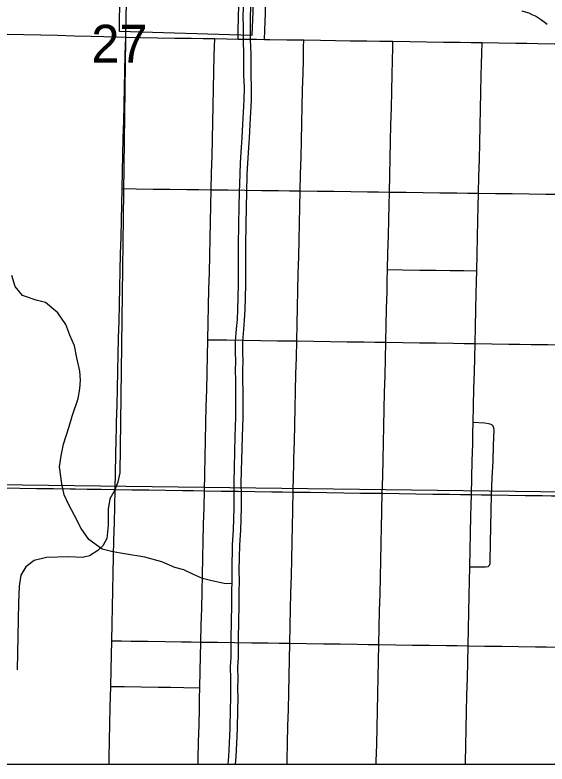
# Model space of a CAD drawing. Extents: x 0 to 34, y 0 to 22.
# Drawn here: x 5.12 to 5.71, y 14.1 to 14.929 of the extents above; entities that cross this region are included whole.
import ezdxf

# ---------------------------------------------------------------- set-up
doc = ezdxf.new("R2010")
doc.units = 0
for name, color, linetype in [('GM_X_City_Street', 7, 'Continuous'), ('GM_X_Corporation', 7, 'Continuous'), ('GM_X_County_Road', 7, 'Continuous'), ('GM_X_Minor_River', 7, 'Continuous'), ('GM_X_Rail_Line', 7, 'Continuous'), ('GM_X_Section_Text', 7, 'Continuous'), ('GM_X_State_Shield', 7, 'Continuous'), ('GM_X_Township_Road', 7, 'Continuous'), ('SH_Data', 7, 'Continuous')]:
    doc.layers.add(name, color=color, linetype=linetype)

msp = doc.modelspace()

# ---------------------------------------------------------------- linework, layer by layer
at = {"layer": 'GM_X_City_Street'}
msp.add_line((5.2326, 14.47067), (5.23264, 14.47263), dxfattribs=at)
for points in [[(5.39671, 14.9023), (5.39702, 14.91248), (5.39758, 14.93111), (5.39815, 14.94975), (5.39871, 14.96838), (5.39927, 14.98702), (5.39984, 15.00565), (5.40022, 15.01854), (5.40061, 15.03142)], [(5.23264, 14.47263), (5.23278, 14.47851), (5.23322, 14.49715), (5.23366, 14.51578), (5.23409, 14.53442), (5.23453, 14.55305), (5.23497, 14.57169), (5.23541, 14.59032), (5.23585, 14.60896), (5.23629, 14.62759), (5.23672, 14.64623), (5.23716, 14.66486), (5.2376, 14.6835), (5.23804, 14.70213), (5.23845, 14.7196), (5.23886, 14.73706), (5.23929, 14.7557), (5.23973, 14.77433), (5.24017, 14.79297), (5.24061, 14.8116), (5.24105, 14.83023), (5.24148, 14.84887), (5.24191, 14.86721), (5.24234, 14.88555), (5.24257, 14.89522), (5.2428, 14.90489)], [(5.42905, 14.43012), (5.42925, 14.4384), (5.42969, 14.45703), (5.43012, 14.47567), (5.43056, 14.4943), (5.431, 14.51294), (5.43144, 14.53157), (5.43187, 14.54999), (5.4323, 14.56841), (5.43274, 14.58705), (5.43317, 14.60568), (5.43362, 14.62432), (5.43405, 14.64295), (5.43449, 14.66159), (5.43493, 14.68022), (5.43537, 14.69886), (5.43578, 14.71671), (5.43621, 14.73456), (5.43664, 14.75319), (5.43708, 14.77183), (5.43751, 14.79046), (5.43795, 14.8091), (5.43839, 14.82773), (5.43883, 14.84637), (5.43926, 14.865), (5.4396, 14.87939), (5.43994, 14.89377), (5.44013, 14.90165)], [(5.52706, 14.39971), (5.5275, 14.41834), (5.52795, 14.43698), (5.52839, 14.45561), (5.52883, 14.47425), (5.52927, 14.49288), (5.5297, 14.51152), (5.53014, 14.53015), (5.53058, 14.54857), (5.53101, 14.56698), (5.53145, 14.58561), (5.53189, 14.60425), (5.53233, 14.62288), (5.53262, 14.63512), (5.5329, 14.64737), (5.53334, 14.666), (5.53379, 14.68464), (5.53423, 14.70327), (5.53458, 14.71828), (5.53494, 14.7333), (5.53538, 14.75194), (5.53582, 14.77057), (5.53626, 14.78921), (5.5367, 14.80784), (5.53714, 14.82648), (5.53758, 14.84511), (5.53802, 14.86375), (5.53837, 14.87845), (5.53871, 14.89315), (5.53888, 14.90019)], [(5.62981, 14.56555), (5.63025, 14.58418), (5.63068, 14.60282), (5.63112, 14.62145), (5.63142, 14.63378), (5.6317, 14.6461), (5.63214, 14.66473), (5.63258, 14.68337), (5.63301, 14.702), (5.63337, 14.71702), (5.63372, 14.73205), (5.63416, 14.75068), (5.63459, 14.76932), (5.63503, 14.78795), (5.63547, 14.80659), (5.63591, 14.82522), (5.63634, 14.84386), (5.63678, 14.86249), (5.63708, 14.87481), (5.63736, 14.88713), (5.63764, 14.89872)], [(5.23886, 14.73706), (5.25443, 14.73686), (5.27307, 14.73663), (5.29171, 14.73639), (5.31035, 14.73615), (5.32397, 14.73599), (5.33758, 14.73581)], [(5.33758, 14.73581), (5.35622, 14.73558), (5.37486, 14.73534), (5.39351, 14.7351), (5.41215, 14.73487), (5.42418, 14.73471), (5.43621, 14.73456), (5.45485, 14.73432), (5.47349, 14.73408), (5.49213, 14.73385), (5.51077, 14.73361), (5.52285, 14.73346), (5.53494, 14.7333)], [(5.53494, 14.7333), (5.55358, 14.73307), (5.57222, 14.73283), (5.59086, 14.73259), (5.6095, 14.73236), (5.62161, 14.7322), (5.63372, 14.73205), (5.65236, 14.73181), (5.671, 14.73157), (5.68964, 14.73134), (5.70829, 14.7311), (5.72064, 14.73095), (5.733, 14.73078)], [(5.5329, 14.64737), (5.54961, 14.64715), (5.56825, 14.64691), (5.58689, 14.64667), (5.60216, 14.64648), (5.61742, 14.64628), (5.6317, 14.6461)], [(5.3338, 14.56984), (5.34436, 14.56969), (5.35492, 14.56954), (5.37356, 14.56927), (5.3922, 14.569), (5.41084, 14.56873), (5.42157, 14.56857), (5.4323, 14.56841), (5.45095, 14.56814), (5.46959, 14.56787), (5.48823, 14.5676), (5.50687, 14.56733), (5.51894, 14.56715), (5.53101, 14.56698)], [(5.53101, 14.56698), (5.54965, 14.56671), (5.56829, 14.56644), (5.58693, 14.56617), (5.60557, 14.5659), (5.61769, 14.56573), (5.62981, 14.56555), (5.64845, 14.56528), (5.66709, 14.56501), (5.67949, 14.56483), (5.69189, 14.56465), (5.71047, 14.56438), (5.72904, 14.56411)], [(5.62589, 14.39828), (5.62633, 14.41692), (5.62676, 14.43555), (5.6272, 14.45419), (5.62748, 14.46605), (5.62776, 14.47798), (5.62819, 14.49662), (5.62863, 14.51525), (5.62907, 14.53389), (5.62944, 14.54972), (5.62981, 14.56555)], [(5.64821, 14.39796), (5.64898, 14.41658), (5.64974, 14.43521), (5.65045, 14.45253), (5.65117, 14.46985), (5.65083, 14.47197), (5.64999, 14.47402), (5.64847, 14.47553), (5.64645, 14.47628), (5.64463, 14.47661), (5.64079, 14.47728), (5.62776, 14.47798)], [(5.23104, 14.40398), (5.23147, 14.42261), (5.23191, 14.44124), (5.23234, 14.45988), (5.2326, 14.47067)], [(5.42838, 14.40113), (5.42881, 14.41976), (5.42905, 14.43012)], [(5.10678, 14.40569), (5.12542, 14.40544), (5.14406, 14.40518), (5.1627, 14.40492), (5.18135, 14.40466), (5.18723, 14.40458)], [(5.18723, 14.40458), (5.19999, 14.4044), (5.21551, 14.40419), (5.23104, 14.40398), (5.24968, 14.40371), (5.26832, 14.40344), (5.28696, 14.40317), (5.3056, 14.4029), (5.3178, 14.40272), (5.33, 14.40255), (5.34864, 14.40228), (5.36728, 14.40201), (5.38592, 14.40174), (5.40457, 14.40148), (5.41647, 14.4013), (5.42838, 14.40113), (5.44702, 14.40086), (5.46566, 14.40059), (5.4843, 14.40033), (5.50294, 14.40005), (5.515, 14.39988), (5.52706, 14.39971)], [(5.22433, 14.1), (5.22449, 14.1071), (5.2249, 14.12573), (5.22531, 14.14437), (5.22572, 14.163), (5.22597, 14.17443), (5.22623, 14.18587), (5.22664, 14.20451), (5.22699, 14.22048), (5.22734, 14.23645), (5.22775, 14.25508), (5.22816, 14.27372), (5.22857, 14.29235), (5.22898, 14.31099), (5.22939, 14.32962), (5.2298, 14.34826), (5.23022, 14.36689), (5.23063, 14.38543), (5.23104, 14.40398)], [(5.4279, 14.3797), (5.42797, 14.38262), (5.42838, 14.40113)], [(5.52659, 14.3783), (5.52665, 14.38122), (5.52706, 14.39971)], [(5.52706, 14.39971), (5.5457, 14.39944), (5.56435, 14.39917), (5.58299, 14.3989), (5.60163, 14.39864), (5.61376, 14.39846), (5.62589, 14.39828), (5.63705, 14.39812), (5.64821, 14.39796), (5.66685, 14.39769), (5.68549, 14.39743), (5.70413, 14.39716), (5.7146, 14.39701), (5.72507, 14.39685)], [(5.6221, 14.2309), (5.62252, 14.24953), (5.62295, 14.26817), (5.62337, 14.2868), (5.62372, 14.30263), (5.62408, 14.31845), (5.62451, 14.33708), (5.62493, 14.35572), (5.62535, 14.37435), (5.62562, 14.38632), (5.62589, 14.39828)], [(5.62408, 14.31845), (5.62946, 14.31838), (5.64138, 14.31822), (5.6444, 14.31861), (5.64595, 14.32026), (5.64662, 14.3221), (5.64654, 14.3256), (5.64697, 14.34424), (5.6474, 14.36287), (5.6478, 14.38041), (5.64821, 14.39796)], [(5.42511, 14.25438), (5.42548, 14.27095), (5.4259, 14.28958), (5.42631, 14.30822), (5.42673, 14.32685), (5.42714, 14.34549), (5.42756, 14.36412), (5.4279, 14.3797)], [(5.52038, 14.1), (5.52045, 14.10314), (5.52087, 14.12177), (5.52128, 14.14041), (5.5217, 14.15904), (5.52212, 14.17768), (5.52253, 14.19631), (5.52293, 14.2143), (5.52333, 14.23229), (5.52374, 14.25093), (5.52416, 14.26956), (5.52458, 14.2882), (5.52499, 14.30683), (5.52541, 14.32547), (5.52583, 14.3441), (5.52624, 14.36273), (5.52659, 14.3783)], [(5.42167, 14.1), (5.42177, 14.10446), (5.42219, 14.12309), (5.4226, 14.14173), (5.42302, 14.16036), (5.42344, 14.179), (5.42385, 14.19763), (5.42425, 14.21565), (5.42465, 14.23368), (5.42507, 14.25231), (5.42511, 14.25438)], [(5.22734, 14.23645), (5.23802, 14.2363), (5.2487, 14.23615), (5.26734, 14.23589), (5.28598, 14.23563), (5.30462, 14.23536), (5.31539, 14.23521), (5.32615, 14.23506), (5.34479, 14.23479), (5.36343, 14.23453), (5.38207, 14.23427), (5.40071, 14.23401), (5.41268, 14.23384), (5.42465, 14.23368), (5.44329, 14.23342), (5.46193, 14.23315), (5.48057, 14.23289), (5.49921, 14.23263), (5.51127, 14.23246), (5.52333, 14.23229)], [(5.52333, 14.23229), (5.54197, 14.23203), (5.56061, 14.23177), (5.57925, 14.23151), (5.59789, 14.23124), (5.61, 14.23107), (5.6221, 14.2309), (5.64074, 14.23064), (5.65938, 14.23038), (5.67802, 14.23012), (5.69667, 14.22985), (5.70911, 14.22968), (5.72155, 14.22951)], [(5.61915, 14.1), (5.61919, 14.10182), (5.61961, 14.12046), (5.62003, 14.13909), (5.62045, 14.15773), (5.62087, 14.17636), (5.62129, 14.195), (5.6217, 14.21295), (5.6221, 14.2309)], [(5.22623, 14.18587), (5.2414, 14.18566), (5.26004, 14.1854), (5.27868, 14.18513), (5.29286, 14.18493), (5.30704, 14.18473), (5.32499, 14.18448)]]:
    msp.add_lwpolyline(points, dxfattribs=at)
at = {"layer": 'GM_X_Corporation'}
for points in [[(5.74537, 15.40679), (5.73134, 14.40091), (4.7262, 14.41378), (4.74513, 15.41881)], [(4.71711, 14.1), (5.72409, 14.1), (5.73134, 14.40091), (4.7262, 14.41378)]]:
    msp.add_lwpolyline(points, close=True, dxfattribs=at)
for points in [[(4.86892, 15.16023), (4.86627, 14.91291), (4.86482, 14.7868), (5.04807, 14.78535), (5.04371, 14.66061), (5.10769, 14.65985), (5.10309, 14.53445), (5.04126, 14.53564), (5.03924, 14.45507), (5.04748, 14.45507), (5.09633, 14.45434), (5.09528, 14.41256), (5.09862, 14.41251), (5.09839, 14.40623), (5.09328, 14.1), (6.26034, 14.1), (6.26105, 14.14125), (6.22094, 14.1423), (6.22387, 14.20233), (6.27047, 14.20234), (6.271, 14.23518), (6.22469, 14.23501), (6.22548, 14.26593), (6.3721, 14.26601)], [(5.39108, 15.11384), (5.3824, 14.90652), (5.23579, 14.9109), (5.23831, 15.15526)], [(2.1, 14.1), (7.72441, 14.1)], [(2.1, 14.1), (7.72441, 14.1)]]:
    msp.add_lwpolyline(points, dxfattribs=at)
at = {"layer": 'GM_X_County_Road'}
for points in [[(5.36727, 14.90273), (5.36746, 14.91006), (5.36795, 14.9287), (5.36843, 14.94733)], [(5.33, 14.40255), (5.33042, 14.42118), (5.33085, 14.43982), (5.33127, 14.45845), (5.33169, 14.47709), (5.33211, 14.49572), (5.33254, 14.51436), (5.33297, 14.53299), (5.33338, 14.55142), (5.3338, 14.56984), (5.33423, 14.58848), (5.33465, 14.60711), (5.33507, 14.62575), (5.33549, 14.64438), (5.33592, 14.66302), (5.33635, 14.68165), (5.33677, 14.70029), (5.33718, 14.71805), (5.33758, 14.73581), (5.338, 14.75445), (5.33843, 14.77308), (5.33885, 14.79172), (5.33927, 14.81035), (5.33969, 14.82899), (5.34012, 14.84762), (5.34055, 14.86626), (5.34096, 14.88429), (5.34139, 14.90312)], [(5.34139, 14.90312), (5.35433, 14.90292), (5.36727, 14.90273)], [(5.32304, 14.1), (5.32317, 14.10578), (5.3236, 14.12441), (5.32403, 14.14305), (5.32446, 14.16168), (5.32472, 14.17308), (5.32499, 14.18448), (5.32542, 14.20311), (5.32578, 14.21909), (5.32615, 14.23506), (5.32658, 14.25369), (5.32701, 14.27233), (5.32744, 14.29096), (5.32786, 14.3096), (5.32829, 14.32823), (5.32872, 14.34687), (5.32915, 14.3655), (5.32957, 14.38402), (5.33, 14.40255)]]:
    msp.add_lwpolyline(points, dxfattribs=at)
at = {"layer": 'GM_X_Minor_River'}
for points in [[(5.37292, 14.93844), (5.37265, 14.92667), (5.37281, 14.9168), (5.37284, 14.9016), (5.37324, 14.88564), (5.37338, 14.87539), (5.37348, 14.86285), (5.37393, 14.84917), (5.37361, 14.83512)], [(5.38202, 14.83493), (5.38234, 14.84921), (5.38189, 14.86302), (5.3818, 14.87548), (5.38165, 14.88581), (5.38125, 14.90172), (5.38122, 14.91687), (5.38107, 14.92664), (5.38133, 14.93839)], [(5.37361, 14.83512), (5.37224, 14.80857), (5.37152, 14.7934), (5.37091, 14.78316), (5.36975, 14.76571), (5.3691, 14.75358), (5.36861, 14.73232), (5.36829, 14.71789), (5.36732, 14.67538), (5.36736, 14.66057), (5.36746, 14.64841), (5.36744, 14.63057), (5.36682, 14.60324), (5.36619, 14.59224), (5.3652, 14.58201), (5.36412, 14.56798), (5.36423, 14.5562), (5.36437, 14.54557), (5.36415, 14.53608), (5.36428, 14.52506), (5.36437, 14.51215), (5.36449, 14.48404), (5.36425, 14.47379), (5.36362, 14.46279), (5.36246, 14.41155), (5.36251, 14.39712), (5.36259, 14.38382), (5.36202, 14.35915), (5.36089, 14.34285), (5.36027, 14.31514), (5.36036, 14.3026), (5.36009, 14.29084), (5.36013, 14.27602), (5.3593, 14.23921), (5.35946, 14.22971), (5.35919, 14.21794), (5.35858, 14.2077), (5.35904, 14.1944), (5.3588, 14.18415), (5.35892, 14.17275), (5.35864, 14.16023), (5.35816, 14.13935), (5.35742, 14.12342), (5.35671, 14.10862), (5.356, 14.1)], [(5.36444, 14.1), (5.3651, 14.10808), (5.36582, 14.12302), (5.36657, 14.13906), (5.36705, 14.16004), (5.36733, 14.1727), (5.36721, 14.1841), (5.36745, 14.19445), (5.367, 14.20759), (5.3676, 14.21759), (5.36787, 14.22968), (5.36771, 14.23918), (5.36854, 14.27594), (5.3685, 14.29075), (5.36877, 14.30254), (5.36868, 14.31507), (5.3693, 14.34246), (5.37043, 14.35876), (5.371, 14.38375), (5.37092, 14.39715), (5.37087, 14.41147), (5.37203, 14.46246), (5.37266, 14.47346), (5.3729, 14.48396), (5.37278, 14.51219), (5.37269, 14.52514), (5.37256, 14.53603), (5.37278, 14.54553), (5.37264, 14.5563), (5.37253, 14.5677), (5.37357, 14.58128), (5.37457, 14.59159), (5.37522, 14.6029), (5.37585, 14.63046), (5.37588, 14.64844), (5.37577, 14.66062), (5.37573, 14.6753), (5.37669, 14.7177), (5.37702, 14.73213), (5.3775, 14.75325), (5.37815, 14.76521), (5.3793, 14.78263), (5.37992, 14.79295), (5.38064, 14.80815), (5.38202, 14.83493)], [(5.36029, 14.29957), (5.35195, 14.29976), (5.33836, 14.30274), (5.3278, 14.30526), (5.31803, 14.30967), (5.30715, 14.31486), (5.29735, 14.31774), (5.2827, 14.32378), (5.26385, 14.32916), (5.24155, 14.33271), (5.2287, 14.33491), (5.21663, 14.33785), (5.20208, 14.34845), (5.19364, 14.36079), (5.18599, 14.37502), (5.17945, 14.38771), (5.17476, 14.39807), (5.172, 14.41029), (5.16939, 14.42896), (5.17118, 14.44107), (5.17376, 14.4543), (5.18027, 14.47352), (5.18357, 14.48522), (5.19008, 14.50481), (5.19184, 14.51541), (5.19282, 14.52488), (5.19191, 14.53515), (5.18882, 14.54966), (5.1861, 14.56301), (5.18105, 14.5749), (5.17639, 14.58678), (5.16758, 14.59952), (5.1538, 14.61085), (5.14363, 14.61375), (5.12856, 14.61866), (5.12045, 14.62872), (5.11655, 14.64097)]]:
    msp.add_lwpolyline(points, dxfattribs=at)
at = {"layer": 'GM_X_Rail_Line'}
for points in [[(5.23124, 14.40396), (5.23458, 14.41239), (5.23676, 14.42256), (5.24302, 14.90275), (5.25165, 15.41214), (5.26723, 16.42373), (5.28297, 17.43133), (5.28986, 17.87281), (5.30759, 19.0241), (5.30572, 19.09621), (5.30112, 19.14915), (5.2883, 19.20664), (5.09526, 19.83998), (5.07238, 19.91573), (5.05866, 19.96318), (5.05132, 20.01977), (5.05835, 20.45243), (5.06838, 20.9)], [(5.23124, 14.40396), (5.22515, 14.39365), (5.22334, 14.38213), (5.22328, 14.36433), (5.22178, 14.34956), (5.21748, 14.34159), (5.21191, 14.33627), (5.20276, 14.33065), (5.19501, 14.32875), (5.17978, 14.32944), (5.15512, 14.32865), (5.14131, 14.32519), (5.13232, 14.31825), (5.12667, 14.309), (5.12473, 14.29705), (5.12415, 14.27832), (5.12241, 14.20414)]]:
    msp.add_lwpolyline(points, dxfattribs=at)
at = {"layer": 'GM_X_State_Shield'}
msp.add_arc((5.66664, 14.87234), 0.06318, 47.18416, 75.83597, dxfattribs=at)
at = {"layer": 'GM_X_Township_Road'}
for points in [[(5.11139, 14.90825), (5.13003, 14.90779), (5.14866, 14.90732), (5.1673, 14.90686), (5.18593, 14.90639), (5.20457, 14.90593), (5.21852, 14.90558), (5.23305, 14.90522), (5.2428, 14.90489), (5.25964, 14.90433), (5.27828, 14.90405), (5.29692, 14.90377), (5.31556, 14.9035), (5.32848, 14.90331), (5.34139, 14.90312)], [(5.34139, 14.90312), (5.35433, 14.90292), (5.36727, 14.90273)], [(5.36727, 14.90273), (5.37741, 14.90258), (5.38755, 14.90243), (5.39671, 14.9023), (5.40265, 14.90221), (5.42129, 14.90193), (5.43071, 14.90179), (5.44013, 14.90165), (5.45877, 14.90138), (5.47511, 14.90113), (5.49145, 14.90089), (5.51009, 14.90062), (5.52448, 14.90041), (5.53888, 14.90019)], [(5.53888, 14.90019), (5.55752, 14.89991), (5.57616, 14.89964), (5.5948, 14.89936), (5.61345, 14.89908), (5.62554, 14.8989), (5.63764, 14.89872), (5.65628, 14.89845), (5.67492, 14.89817), (5.68712, 14.89799), (5.69931, 14.89781), (5.71782, 14.89753), (5.73696, 14.89725)]]:
    msp.add_lwpolyline(points, dxfattribs=at)
at = {"layer": 'SH_Data'}
msp.add_line((2.1, 14.1), (8.9, 14.1), dxfattribs=at)
msp.add_line((2.1, 14.1), (8.9, 14.1), dxfattribs=at)

# ---------------------------------------------------------------- texts
at = {"layer": 'GM_X_Section_Text'}
msp.add_text('27', height=0.041856, rotation=0.00001, dxfattribs=at).set_placement((5.20471, 14.87666))

doc.saveas('drawing.dxf')
